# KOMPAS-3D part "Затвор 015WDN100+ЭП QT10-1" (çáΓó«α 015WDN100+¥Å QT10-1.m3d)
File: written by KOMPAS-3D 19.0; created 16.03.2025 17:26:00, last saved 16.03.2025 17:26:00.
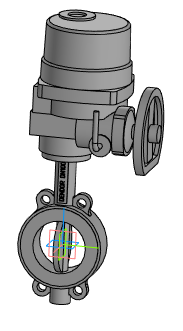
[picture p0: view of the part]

Document properties: Полное имя файла: Затвор 015WDN100+ЭП QT10-1.a3d

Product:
- Part/product: Затвор 015WDN100+ЭП QT10-1
    Масса: 47.3712

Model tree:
1. Операция без истории:1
